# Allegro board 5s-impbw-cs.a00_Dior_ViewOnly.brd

Outline 190 x 92 mm; copper layers: TOP, GND1, IN1, IN2, VCC, IN3, GND2, BOTTOM. Coordinates in mm from the lower left corner of the outline.
Outline path: 0,92 190,92 190,13 188,13 arc(187.29,12.71) 187,12 187,4 180,4 180,8 arc(176,12) 172,8 172,0 119,0 arc(118.71,0.71) 118,1 96,1 arc(95.29,0.71) 95,0 42,0 42,8 arc(38,12) 34,8 34,4 28,4 arc(27.29,3.71) 27,3 27,0 2,0 2,8 arc(1.71,8.71) 1,9 0,9 0,49.7 1.5,49.7 arc(2.21,49.99) 2.5,50.7 2.5,70.5 arc(2.21,71.21) 1.5,71.5 0,71.5 0,92

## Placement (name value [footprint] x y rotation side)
AC1  -  [MX_C0402]  52.53 68.01 90 bottom
AC2  -  [MX_C0402]  50.38 58 0 top
AC3  -  [MX_C0402]  50.24 55.82 0 top
AC4  -  [MX_C0402]  49.1 64.79 270 bottom
AR1  -  [MX_R0402]  50.78 67.28 0 bottom
AR2  -  [MX_R0402]  48.13 57.8 0 top
AR3  -  [MX_R0402]  48.08 56.51 0 top
AR4  -  [MX_R0402]  50.15 64.82 270 bottom
AT2  -  [MX_TPC26B_S4_68]  48.01 63.24 0 top
AT3  -  [MX_TPC26B_S4_68]  50.42 62.63 0 top
AT4  -  [MX_TPC26B_S4_68]  46.2 63.29 0 top
AT6  -  [MX_TPC26B_S4_68]  36.58 63.29 180 bottom
AT9  -  [MX_TPC26B_S4_68]  30.2 61.16 180 bottom
C1  -  [MX_C0402_SMALL]  86.01 22.37 270 top
C2  -  [MX_C0603_SMALL]  87.83 68.99 0 top
C3  -  [MX_C0603_SMALL]  87.83 67.74 0 top
C4  -  [MX_C0603_SMALL]  87.38 38.12 90 top
C5  -  [MX_C0603_SMALL]  89.45 62.27 0 top
C6  -  [MX_C0603_SMALL]  86.76 25.52 0 top
C7  -  [MX_C0603_SMALL]  86.76 24.32 0 top
C8  -  [MX_C0603_SMALL]  69.88 79.95 270 top
C9  -  [MX_C0603_SMALL]  69.88 82.22 90 top
C10  -  [MX_C0402]  69.93 72.81 90 top
C11  -  [MX_C0402]  69.47 64.84 180 top
C12  -  [MX_C0402]  89.25 64.47 0 top
C13  -  [MX_C0402]  69.77 41.38 270 top
C14  -  [MX_C0402]  69.47 62.76 180 top
C15  -  [MX_C0402]  69.34 59 0 top
C16  -  [MX_C0402]  68.94 20.87 270 top
C17  -  [MX_C0402]  86.51 19.47 0 top
C18  -  [MX_C0402]  86.7 26.66 0 top
C19  -  [MX_C0402]  68.35 32.53 270 top
C20  -  [MX_C0402]  69.01 70.02 180 top
C21  -  [MX_C0402]  89.25 63.43 0 top
C22  -  [MX_C0402]  86.67 40.85 270 top
C23  -  [MX_C0402]  59.96 82.05 90 top
C24  -  [MX_C0402]  89.33 40.86 270 top
C25  -  [MX_C0402]  86.79 54.14 90 top
C26  -  [MX_C0402]  91.23 52.95 90 top
C27  -  [MX_C0402]  90.17 52.93 90 top
C28  -  [MX_C0402]  70.87 47.11 270 top
C29  -  [MX_C0402]  87.87 54.13 90 top
C30  -  [MX_C0402]  67.59 61.71 180 top
C31  -  [MX_C0402]  69.37 48.81 0 top
C32  -  [MX_C0402]  87.28 60.14 270 top
C33  -  [MX_C0402]  69.93 34.38 90 top
C34  -  [MX_C0402]  69.93 31.11 270 top
C35  -  [MX_C0402]  69.93 28.06 270 top
C36  -  [MX_C0402]  69.79 23.98 270 top
C37  -  [MX_C0402]  68.86 72.81 90 top
C38  -  [MX_C0402]  86.7 27.7 0 top
C39  -  [MX_C0402]  68.99 66.79 270 top
C40  -  [MX_C0402]  89.23 65.5 0 top
C41  -  [MX_C0402]  69.47 63.8 180 top
C42  -  [MX_C0402]  74.63 17.28 270 top
C43  -  [MX_C0402]  50.14 19.8 180 top
C45  -  [MX_C0402]  54.47 15.33 90 top
C46  -  [MX_C0402]  53.33 20.25 270 top
C48  -  [MX_C0402_SMALL]  165.25 80.03 270 bottom
C49  -  [MX_C0402]  46.2 72.37 180 bottom
C50  -  [MX_C0402]  48.08 72.37 0 bottom
C51  -  [MX_C0402_SMALL]  50.24 70.1 270 top
C52  -  [MX_C0402_SMALL]  52.16 67.5 180 top
C53  -  [MX_C0402_SMALL]  138.31 79.7 90 bottom
C54  -  [MX_C0402_SMALL]  164.07 16.94 90 top
C55  -  [MX_C0402_SMALL]  168.54 22.89 180 top
C56  -  [MX_C0402_SMALL]  167.24 27.84 180 top
C57  -  [MX_C0402_SMALL]  156.59 19.37 270 top
C58  -  [MX_C0402_SMALL]  155.73 19.43 270 top
C59  -  [MX_C0402_SMALL]  161.36 29.61 270 top
C60  -  [MX_C0402]  167.29 29.51 90 top
C61  -  [MX_C0402_SMALL]  166.11 29.61 90 top
C62  -  [MX_C0402_SMALL]  165.12 29.61 90 top
C63  -  [MX_C0402_SMALL]  164.13 29.61 90 top
C64  -  [MX_C0402_SMALL]  163.14 29.61 90 top
C65  -  [MX_C0402_SMALL]  169.14 23.73 180 top
C66  -  [MX_C0402_SMALL]  169.14 24.65 180 top
C67  -  [MX_C0402]  168.43 26.77 0 top
C68  -  [MX_C0402_SMALL]  159.55 16.36 90 top
C69  -  [MX_C0402_SMALL]  95.85 85.54 0 bottom
C70  -  [MX_C0402_SMALL]  113.11 78.6 180 top
C71  -  [MX_C0402_SMALL]  99.93 71.76 0 bottom
C72  -  [MX_C0402_SMALL]  117.3 87.13 180 bottom
C73  -  [MX_C0805_SMALL]  117.21 83.15 90 bottom
C74  -  [MX_C0402_SMALL]  117.27 85.02 180 bottom
C75  -  [MX_C0805_SMALL]  120.14 71.01 180 bottom
C76  -  [MX_C0402_SMALL]  106.15 71.01 90 bottom
C77  -  [MX_C0402_SMALL]  96.74 78.76 90 bottom
C78  -  [MX_C0402_SMALL]  96.72 80.38 270 bottom
C79  -  [MX_C0603_SMALL]  96.73 80.66 180 top
C80  -  [MX_C0402]  95.08 72.14 180 bottom
C81  -  [MX_C0402]  96.79 73.81 0 bottom
C82  -  [MX_C0402_SMALL]  115.01 82.64 90 top
C83  -  [MX_C0402_SMALL]  117.3 87.98 180 bottom
C84  -  [MX_C0402_SMALL]  65.51 85.44 90 bottom
C85  -  [MX_C0402_SMALL]  77.16 85.83 0 top
C86  -  [MX_C0402]  77.17 84.5 180 top
C87  -  [MX_C0402_SMALL]  14.56 68.5 180 bottom
C88  -  [MX_C0402_SMALL]  105.34 70.99 90 top
C91  -  [MX_C0603_SMALL]  182.32 65.24 90 top
C92  -  [MX_C0402]  183.47 65.12 90 top
C93  -  [MX_C0402]  182.58 62.96 270 top
C94  -  [MX_C0603_SMALL]  183.39 58.51 90 top
C95  -  [MX_C0402]  183.06 55.59 180 top
C96  -  [MX_C0402]  183.06 56.74 180 top
C97  -  [MX_C0402_SMALL]  184.1 29.76 270 bottom
C98  -  [MX_C0402_SMALL]  186.97 20.48 180 bottom
C99  -  [MX_C0402_SMALL]  184.1 27.86 90 bottom
C100  -  [MX_C0402_SMALL]  145.49 80.16 0 bottom
C101  -  [MX_C0402_SMALL]  145.38 90.38 0 bottom
C102  -  [MX_C0402_SMALL]  148.56 85.97 90 bottom
C103  -  [MX_C0402_SMALL]  148.56 84.38 270 bottom
C111  -  [MX_C0402]  26.63 81.48 180 bottom
C112  -  [MX_C0603_SMALL]  33.84 83.82 0 bottom
C113  -  [MX_C0402]  28.15 82.34 270 bottom
C114  -  [MX_C0402_SMALL]  41.1 90.01 270 bottom
C115  -  [MX_C0603]  16.38 68.39 90 bottom
C116  -  [MX_C0402]  20.5 63.38 90 top
C121  -  [MX_C0402_SMALL]  96.22 22.19 0 top
C122  -  [MX_C0402_SMALL]  96.22 21.27 0 top
C123  -  [MX_C0402_SMALL]  96.19 20.24 0 top
C124  -  [MX_C0402_SMALL]  96.19 19.35 0 top
C125  -  [MX_C0603]  102.24 9.9 180 bottom
C126  -  [MX_C0402_SMALL]  104.19 35.91 270 bottom
C127  -  [MX_C0402_SMALL]  103.33 35.91 90 bottom
C128  -  [MX_C0402]  149.27 12.15 90 top
C129  -  [MX_C0402]  150.36 12.15 90 top
C130  -  [MX_C0402]  154.37 12.68 90 top
C131  -  [MX_C0402]  155.47 12.68 90 top
C132  -  [MX_C0402_SMALL]  163.78 11.9 180 top
C133  -  [MX_C0402_SMALL]  163.78 11.07 180 top
C134  -  [MX_C0402]  167.63 14.05 90 top
C135  -  [MX_C0402_SMALL]  165.38 11.48 0 top
C136  -  [MX_C0402]  166.57 14.05 90 top
C137  -  [MX_C0402_SMALL]  167.03 10.83 180 top
C138  -  [MX_C0603_SMALL]  145.52 12.31 180 top
C139  -  [MX_C0603_SMALL]  145.52 13.61 180 top
C140  -  [MX_C0402]  147.64 13.26 0 top
C141  -  [MX_C0402]  147.64 12.17 0 top
C142  -  [MX_C0402]  147.97 9.37 270 top
C143  -  [MX_C0402]  146.87 9.37 270 top
C144  -  [MX_C0402_SMALL]  169.29 38.18 0 top
C145  -  [MX_C0402_SMALL]  168.69 14.01 270 top
C146  -  [MX_C0402_SMALL]  174.9 35.07 90 top
C147  -  [MX_C0402_SMALL]  175.94 69.64 90 bottom
C148  -  [MX_C0603]  173.92 64.74 90 bottom
C149  -  [MX_C0402_SMALL]  177.12 39.39 180 bottom
C150  -  [MX_C0402_SMALL]  175.08 39.39 180 bottom
C151  -  [MX_C0402_SMALL]  78.18 9.49 270 bottom
C152  -  [MX_C0805_SMALL]  81.61 8.35 180 bottom
C153  -  [MX_C0402]  61.84 6.99 270 bottom
C154  -  [MX_C0402_SMALL]  6.1 52.98 0 top
C155  -  [MX_C0805_SMALL]  7.39 51.12 90 top
C156  -  [MX_C0402]  159.72 36.16 180 top
C157  -  [MX_C0402_SMALL]  136.19 75.23 270 bottom
C158  -  [MX_C0402_SMALL]  135.31 75.23 270 bottom
C159  -  [MX_C0402]  127.34 70.27 180 bottom
C160  -  [MX_C0402]  129.7 70.3 180 bottom
C161  -  [MX_C0402]  124.93 70.27 180 bottom
C162  -  [MX_C0603]  170.41 81.14 0 top
C163  -  [MX_C0402_SMALL]  168.56 80.97 90 top
C164  -  [MX_C0603]  160.2 86.44 180 top
C165  -  [MX_C0402_SMALL]  163.02 86.2 270 top
C171  -  [MX_C0402_SMALL]  154.92 58.23 270 top
C172  -  [MX_C0603]  157.04 58.47 0 top
C173  -  [MX_C0402_SMALL]  157.94 53.2 180 top
C176  -  [MX_C0402_SMALL]  7.7 76.17 0 top
C177  -  [MX_C0402_SMALL]  9.93 88.18 270 bottom
C178  -  [MX_C0402_SMALL]  179.66 78.33 0 top
C179  -  [MX_C0402_SMALL]  179.86 75.58 90 bottom
C180  -  [MX_C0402_SMALL]  173.56 85.06 0 bottom
C181  -  [MX_C0402_SMALL]  173.56 86.33 0 bottom
C182  -  [MX_C0402_SMALL]  171.35 85.01 0 top
C183  -  [MX_C0402_SMALL]  179.05 80.15 90 bottom
C184  -  [MX_C0402_SMALL]  179.91 80.15 90 bottom
C185  -  [MX_C0402_SMALL]  173.56 84.17 0 bottom
C186  -  [MX_C0402]  179.27 82.82 0 bottom
C187  -  [MX_C0402]  177.37 82.82 180 bottom
C190  -  [MX_C0402_SMALL]  158.8 78.91 270 bottom
C191  -  [MX_C0402_SMALL]  163.02 68.85 90 bottom
C192  -  [MX_C0402_SMALL]  151.39 68.67 0 bottom
C193  -  [MX_C0402_SMALL]  150.99 69.98 90 bottom
C194  -  [MX_C0402_SMALL]  155.93 76.74 270 top
C195  -  [MX_C0402]  150.2 76.27 180 bottom
C196  -  [MX_C0402]  173.47 47.46 0 top
C197  -  [MX_C0402]  173.47 48.51 0 top
C198  -  [MX_C0402]  173.05 53.97 180 top
C199  -  [MX_C0402_SMALL]  180.71 49.24 180 top
C200  -  [MX_C0402_SMALL]  180.71 50.13 180 top
C201  -  [MX_C0402]  29.29 21.43 270 top
C400  -  [MX_C0402_SMALL]  165.68 65.83 180 top
C420  -  [MX_C0402]  183.01 42.06 0 top
C430  -  [MX_C0603]  120.22 3.65 180 bottom
C431  -  [MX_C0402_SMALL]  8.21 77.82 0 top
C432  -  [MX_C0402_SMALL]  10.24 81.25 180 top
C433  -  [MX_C0402_SMALL]  42.01 90.01 270 bottom
C1174  -  [MX_C0603]  57.35 56.74 180 top
C1175  -  [MX_C0603]  54.48 56.68 0 top
C1176  -  [MX_C0603]  59.56 57.11 90 top
C1177  -  [MX_C0603]  54.88 51.97 90 bottom
C1178  -  [MX_C0603]  47.22 34.2 270 bottom
C1179  -  [MX_C0603]  47.06 40.92 90 bottom
C1180  -  [MX_C0402]  46.95 43.36 270 bottom
C1181  -  [MX_C0402]  46.94 38.5 270 bottom
C1182  -  [MX_C0402]  46.94 36.57 90 bottom
C1183  -  [MX_C0402]  87.83 66.59 0 top
C1184  -  [MX_C0402]  76.15 18.88 180 top
C1185  -  [MX_C0402]  80.7 18.86 180 top
C1186  -  [MX_C0402]  69.93 37.89 270 top
C1187  -  [MX_C0402]  74.47 50.23 180 top
C1188  -  [MX_C0402]  73 18.86 180 top
C1189  -  [MX_C0402]  47.54 17.15 270 top
C1190  -  [MX_C0402]  47.88 20.44 0 top
C1191  -  [MX_C0402]  46.48 17.15 270 top
C1192  -  [MX_C0603]  58.18 19.21 90 top
C1193  -  [MX_C0402]  56.84 19.02 90 top
C1194  -  [MX_C0402]  57.99 16.47 270 top
C1195  -  [MX_C0603]  59.32 16.25 270 top
C9200  -  [MX_C0603_SMALL]  154.31 65.33 90 top
C9206  -  [MX_C0402]  155.38 17.66 270 top
C9207  -  [MX_C0402_SMALL]  157.37 17.73 90 top
C9209  -  [MX_C0402_SMALL]  156.41 22.65 0 top
C9210  -  [MX_C0402_SMALL]  168.27 25.66 180 top
C9211  -  [MX_C0402_SMALL]  159.44 29.58 270 top
C9212  -  [MX_C0402_SMALL]  168.53 21.85 180 top
C9213  -  [MX_C0402_SMALL]  162.2 29.61 270 top
C9214  -  [MX_C0402_SMALL]  161.22 16.42 90 top
C9215  -  [MX_C0402_SMALL]  158.66 16.36 90 top
C9217  -  [MX_C0402]  183.03 43.15 0 top
C9218  -  [MX_C0402]  183.03 45.72 0 top
C9219  -  [MX_C0402]  183.03 46.81 0 top
C9220  -  [MX_C0402_SMALL]  6.41 81.09 270 top
CA10  -  [MX_C0402_SMALL]  164.98 54.68 90 top
CA11  -  [MX_C0402_SMALL]  161.37 53.35 0 top
CA12  -  [MX_C0603_SMALL]  163.35 53.17 0 top
CA13  -  [MX_C0603_SMALL]  165.08 59.32 90 top
CB1  -  [MX_R0402_SMALL]  124.92 32.29 270 top
CB2  -  [MX_R0402_SMALL]  125.69 43.65 180 top
CB3  -  [MX_C0402_SMALL]  125.78 32.27 90 top
CB4  -  [MX_R0402_SMALL]  129.95 32.3 270 top
CB5  -  [MX_C0402_SMALL]  130.01 43.75 180 top
CB6  -  [MX_R0402_SMALL]  128.46 43.75 180 top
CB7  -  [MX_C0603_SMALL]  96.29 89.74 90 bottom
CE1  -  [MX_C7343D_H75]  96.85 65.49 270 bottom
CKC1  -  [MX_C0402]  15.63 47.99 90 bottom
CKC2  -  [MX_C0402]  15.64 46.09 270 bottom
CKC3  -  [MX_C0402]  35.13 74.44 270 top
CKC4  -  [MX_C0402]  38.36 78.95 90 bottom
CKC5  -  [MX_C0402]  149.3 71.48 270 bottom
CKC6  -  [MX_C0402]  149.29 73.53 90 bottom
CKC7  -  [MX_C0402]  36.3 74.41 90 top
CKR1  -  [MX_R0402]  16.72 46.95 90 bottom
CKR2  -  [MX_R0402]  12.83 39.86 270 bottom
CKR3  -  [MX_R0402]  35.25 72.14 90 top
CKR4  -  [MX_R0402]  38.58 75.23 90 bottom
CKR5  -  [MX_R0402]  36.28 72.14 90 top
CKRN1  -  [MX_2R4P0402_H18]  16 42.87 270 bottom
CKRN2  -  [MX_2R4P0402_H18]  39.83 71.25 0 top
CKX1  -  [MX_XTAL_4P_126X98_HELE]  13.3 46.78 90 bottom
CN1  -  [MX_FPC_CON_5P_39_2HOLD_RA]  25 85 0 bottom
CON1  -  [MX_WTOB_2P_49_2H_ACES]  167.38 84.9 180 bottom
CON2  -  [MX_FPC_26P_20_4HD_RA_PANASO]  103.08 85.62 180 top
CON3  -  [MX_SATA_CON_22P_50_4H_RA_P2]  188.32 56.53 270 bottom
CON4  -  [MX_WTOB_4P_31_2H_RA]  186.11 17.2 180 bottom
CON5  -  [MX_FPC_1X12P_20_2H]  86.71 78.56 180 top
CON6  -  [MX_WTOB_11P_31_2HOLD_ACES]  156 85.99 90 bottom
CON7  -  [MX_WTOB_4P_49_RA]  13 65.5 90 bottom
CON8  -  [MX_WTOB_9P_59_2HD_RA_ACES]  127.01 79.4 0 bottom
CON9  -  [MX_FPC_7P_20_2HOLD_RA_ENT_T]  134 7.8 180 bottom
CON10  -  [MX_BTOB_60P_20_F_PANA]  6 81.99 270 bottom
CON11  -  [MX_FPC_18P_20_2HD_RA_ACE_B]  181 88 0 bottom
CONSATA  -  [MX_MINI_PCI_67P_20_4HD_FOXN]  101.38 23.08 270 bottom
CONWIFI  -  [MX_MINI_PCI_67P_20_4H_FXN]  175.43 51.1 90 bottom
CR1  -  [MX_LED_2P_63X31_H16]  127.52 85.75 0 top
CR2  -  [MX_LED_2P_63X31_H16]  112.96 85.74 0 top
CR3  -  [MX_LED_2P_63X31_H16]  113.75 77.12 0 top
CR4  -  [MX_LED_2P_63X31_H16]  120.91 85.74 0 top
CR5  -  [MX_LED_2P_63X31_H16]  117.43 77.17 0 top
CR6  -  [MX_LED_2P_63X31_H16]  120.99 77.19 0 top
CR7  -  [MX_LED_2P_63X31_H16]  117.61 85.74 0 top
CR8  -  [MX_LED_2P_63X31_H16]  110.39 77.02 0 top
CR9  -  [MX_LED_2P_63X31_H16]  124.19 85.75 0 top
CX3  -  [MX_C0402]  177.01 47.37 90 top
CX4  -  [MX_C0402]  178.11 47.37 90 top
D1  -  [MX_SOT323]  167.41 79.55 0 bottom
D2  -  [MX_SOD323_H37]  49.99 80.87 270 top
D3C5  -  [MX_C0402]  58.95 77.98 270 top
D3C7  -  [MX_C0402]  69.79 25.99 90 top
D3C8  -  [MX_C0402]  60 77.96 270 top
D3CE2  -  [MX_C0603_SMALL]  56.21 56.4 90 bottom
D3CE3  -  [MX_C0603_SMALL]  56.23 51.88 90 bottom
D3CE4  -  [MX_C0603_SMALL]  54.84 55.47 270 bottom
D3CE5  -  [MX_C0603_SMALL]  69.09 71.19 180 top
D3CE6  -  [MX_C0603_SMALL]  56.54 49.34 270 bottom
D3CE7  -  [MX_C0603_SMALL]  67.67 57.01 180 top
D3CE8  -  [MX_C0603_SMALL]  69.57 50.49 270 top
D3CE9  -  [MX_C0603_SMALL]  56.21 54.08 270 bottom
D3CE20  -  [MX_C0402]  86.51 20.54 0 top
D3CE21  -  [MX_C0402]  68.73 23.99 270 top
D3CE22  -  [MX_C0402]  56.64 41.54 270 bottom
D3CE23  -  [MX_C0402]  88.27 31.72 90 top
D3CE24  -  [MX_C0402]  88.34 60.14 270 top
D3CE25  -  [MX_C0402]  68.86 28.06 270 top
D3CE26  -  [MX_C0402]  69.19 52.72 0 top
D3CE27  -  [MX_C0402]  56.65 46.12 90 bottom
D3CE28  -  [MX_C7343D_H79]  101.8 65.48 270 bottom
D3CE36  -  [MX_C0402]  88.94 54.13 90 top
D3CE37  -  [MX_C0402]  87.71 40.85 270 top
D3CE38  -  [MX_C0402]  68.68 81.22 90 top
D3CE39  -  [MX_C0402]  59.97 80.15 270 top
D3CE40  -  [MX_C0603_SMALL]  61.21 82.14 90 top
D3CE41  -  [MX_C0603_SMALL]  61.2 79.94 270 top
D4  -  [MX_SOD323_H37]  9.98 82.77 180 top
D5  -  [MX_S0402_AMAZ]  117.9 71 270 bottom
D6  -  [MX_SOD323_H37]  102.31 79.09 0 top
D7  -  [MX_SOD323_H37]  94.09 86.27 90 bottom
D8  -  [MX_SOT323]  107.51 71.82 0 top
D9  -  [MX_SOD323_H35]  187.05 23.3 90 bottom
D10  -  [MX_S0402_AMAZ]  21.45 82.52 180 bottom
D11  -  [MX_S0402_AMAZ]  31.57 89.88 90 bottom
D12  -  [MX_S0402_AMAZ]  31.57 88.1 270 bottom
D13  -  [MX_SOD323_H37]  14.91 60.39 270 bottom
D14  -  [MX_SOD323_H37]  177.5 63.09 270 top
D15  -  [MX_SOT323]  57.39 10.07 0 bottom
D16  -  [MX_S0402_AMAZ]  64.41 7.21 90 bottom
D17  -  [MX_ESD_2P_33_39X24_AMA]  79.45 9.49 90 bottom
D18  -  [MX_SOT323]  157.43 38.41 90 top
D19  -  [MX_ESD_2P_33_39X24_AMA]  5.92 50.87 270 top
D20  -  [MX_S0402_AMAZ]  125.52 71.47 180 bottom
D21  -  [MX_S0402_AMAZ]  127.55 71.46 180 bottom
D22  -  [MX_S0402_AMAZ]  129.58 71.44 180 bottom
D24  -  [MX_SOD323_H37]  151.52 78.98 180 bottom
D9200  -  [MX_SOD323_H37]  153.96 62.07 90 top
D9201  -  [MX_SOT323]  81.16 89.57 180 bottom
DIMM1  -  [MX_DDR3_DIMM_204P_24_4HL_DA]  63.6 48.5 90 bottom
E2  -  [MX_HD_2X5P_50_K1K3K5K6K79_J]  89.61 85.5 0 bottom
F1  -  [MX_POLYSWITCH_2P_1206]  33.81 85.87 180 bottom
F3CB4  -  [MX_C0603]  134.82 81.75 180 top
F3J1  -  [MX_FPC_10P_20_2H_RA_AC_H79]  135.79 85.28 180 top
F3R2  -  [MX_R0402]  137.57 82.52 90 bottom
F3R3  -  [MX_R0402]  140.05 80.15 0 bottom
F3R7  -  [MX_R0402]  137.56 89.62 90 bottom
F3R8  -  [MX_R0402]  140.01 79.04 0 bottom
F3R9  -  [MX_R0402]  137.56 84.85 270 bottom
F3R10  -  [MX_R0402]  142.71 79.47 270 bottom
F3R11  -  [MX_R0402]  143.84 79.5 270 bottom
F3R13  -  [MX_R0402]  139.82 82.94 180 top
F3R14  -  [MX_R0402]  136.86 80.99 90 top
F3U1  -  [MX_SOIC_8P_50_213X311]  141.12 85.66 0 bottom
GC1  -  [MX_C0402]  78.44 13.05 90 top
GC2  -  [MX_C0402]  81.2 13.05 90 top
GC3  -  [MX_C0402]  93.51 5.4 90 bottom
GC4  -  [MX_C0402]  97.13 7.75 180 bottom
GR1  -  [MX_R0402]  26.24 23.46 90 bottom
GR2  -  [MX_R0402]  23.06 25.11 270 top
GR3  -  [MX_R0402]  43.21 23.94 270 top
GR4  -  [MX_R0402]  59.13 4.92 0 top
GR5  -  [MX_R0402]  82.7 13.05 270 top
GR6  -  [MX_R0402]  80.6 16.02 270 top
GR7  -  [MX_R0402]  62.05 4.92 180 top
GR8  -  [MX_R0402]  70.1 15.1 0 top
GR10  -  [MX_R0402]  58.6 6.06 0 top
GR11  -  [MX_R0402]  70.1 16.22 0 top
GR12  -  [MX_R0402]  62.05 5.96 0 top
GR13  -  [MX_R0402]  58.52 7.15 180 top
GR14  -  [MX_R0402]  121.62 27.04 270 top
GR15  -  [MX_R0402]  81.75 15.99 270 top
GR16  -  [MX_R0402]  83.81 15.98 270 top
GR17  -  [MX_R0402]  62.05 8.18 180 top
GR18  -  [MX_R0402]  62.05 7.15 180 top
GR19  -  [MX_R0402]  58.88 8.35 180 top
GR20  -  [MX_R0402]  83.92 13.05 270 top
GR21  -  [MX_R0402]  84.84 15.99 270 top
GR22  -  [MX_R0402]  85.1 12.99 90 top
GR23  -  [MX_R0402]  82.78 15.99 90 top
GR24  -  [MX_R0402]  99.56 8.13 0 bottom
GR25  -  [MX_R0402]  98.94 9.93 90 bottom
GR26  -  [MX_R0402]  93.69 9.78 90 bottom
GR27  -  [MX_R0402]  100.11 9.94 270 bottom
GR28  -  [MX_R0402]  32.67 18.85 90 bottom
GR29  -  [MX_R0402]  33.73 18.85 90 bottom
GR30  -  [MX_R0402]  31.35 18.85 90 bottom
GR31  -  [MX_R0402]  34.88 24.1 90 bottom
GR32  -  [MX_R0402]  32.46 24.1 90 bottom
GR33  -  [MX_R0402]  33.73 24.1 90 bottom
GR34  -  [MX_R0402]  31.19 24.1 90 bottom
GR35  -  [MX_R0402]  33.73 21.18 90 bottom
GR36  -  [MX_R0402]  31.35 21.18 90 bottom
GR37  -  [MX_R0402]  36.02 24.1 270 bottom
GR38  -  [MX_R0402]  32.46 21.18 90 bottom
GR39  -  [MX_R0402]  165.93 16.18 90 top
GU1  -  [MX_SOIC_14P_26_201X252]  88.82 5.88 90 bottom
GU2  -  [MX_SC70_C5]  96.41 9.64 180 bottom
H1  -  [MX_SMT_NUT_CT197B63D47_H102]  41.83 22.38 180 bottom
H2  -  [MX_SMT_NUT_CT197B63D47_H102]  21.83 22.38 180 bottom
H3  -  [MX_SMT_NUT_CT197B63D47_H102]  21.83 78.78 180 bottom
H4  -  [MX_SMT_NUT_CT197B63D47_H102]  41.83 78.78 180 bottom
H9  -  [MX_SMT_NUT_CT217B160D130]  147.18 51.1 180 bottom
H11  -  [MX_SMT_NUT_CT217B160D130]  179.63 23.07 180 bottom
H19  -  [MX_TPC26B_S4_68]  35.05 68.03 180 bottom
H6505  -  [NB_H_2D_D87N_DO83X102_P2_V4]  187 80.5 0 top
H6506  -  [NB_H_2D_D87N_D83_M2_P2_V4]  183.5 10.5 0 top
H6507  -  [NB_H_S276D87N_M2_P2_V4#2]  98 47.49 0 top
H6508  -  [NB_H_S276D87N_M2_P2_V4]  15 88.5 0 top
H6509  -  [NB_H_2D_DO102X83_D87N_P2_V4]  5.5 3 0 top
H6510  -  [MX_NUT_CT217B118D47_H165]  13 79 180 bottom
H6511  -  [MX_HOLE_C118D118N]  141.63 23.08 0 top
H6512  -  [MX_HOLE_C59D59N]  146.03 23.08 0 top
HC1  -  [MX_C0402]  67.42 68.09 90 top
HC3  -  [MX_C0402]  15.9 31.03 180 bottom
HC5  -  [MX_C0805]  50.32 59.04 270 bottom
HC6  -  [MX_C0402]  34.11 54.78 0 top
HC7  -  [MX_C0402]  99 4.18 270 bottom
HC8  -  [MX_C0402_SMALL]  16.03 27.83 180 bottom
HQ1  -  [MX_SOT23_H43]  39.12 17.9 0 bottom
HQ2  -  [MX_SOT23_H43]  66.3 65.46 180 top
HQ3  -  [MX_SOT23_H43]  77.36 89.19 180 bottom
HR2  -  [MX_R0402]  27.56 21.05 90 bottom
HR3  -  [MX_R0402]  26.52 21.05 90 bottom
HR4  -  [MX_R0402]  27.48 23.46 90 bottom
HR5  -  [MX_R0402]  19.58 26.05 0 top
HR6  -  [MX_R0402]  41.85 18.06 90 bottom
HR7  -  [MX_R0402]  45.59 23.94 270 top
HR8  -  [MX_R0402]  46.75 23.94 270 top
HR9  -  [MX_R0402]  44.35 23.94 270 top
HR10  -  [MX_R0402]  63.55 70.2 270 top
HR11  -  [MX_R0402]  62.03 68.9 180 top
HR12  -  [MX_R0402]  67.26 71.29 270 top
HR13  -  [MX_R0402]  62.8 66.72 180 top
HR14  -  [MX_R0402]  62.56 64.09 270 top
HR15  -  [MX_R0402]  63.6 64.09 270 top
HR16  -  [MX_R0402]  21.75 55.14 90 top
HR21  -  [MX_R0402_SHORT]  15.86 32.16 0 bottom
HR22  -  [MX_R0402]  28.91 21.2 90 bottom
HR23  -  [MX_R0402]  28.91 18.05 270 bottom
HR24  -  [MX_R0402]  28.65 23.46 90 bottom
HR27  -  [MX_R0402_SHORT]  15.76 29.9 0 bottom
HR28  -  [MX_R0402_SHORT]  26.48 24.15 90 top
HR29  -  [MX_R0402_SHORT]  15.86 28.83 0 bottom
HR31  -  [MX_R0402]  26.48 21.46 270 top
HR32  -  [MX_R0805]  52.37 58.81 270 bottom
HR33  -  [MX_R0805]  12.37 30.86 0 bottom
HR34  -  [MX_R0805]  66.93 17.9 0 top
HR37  -  [MX_R0402]  37.67 24.1 90 top
HR38  -  [MX_R0402]  36.53 24.1 90 top
HR39  -  [MX_R0402]  31.95 24.1 90 top
HR40  -  [MX_R0402]  33.1 24.1 90 top
HR41  -  [MX_R0402]  34.24 24.1 90 top
HR42  -  [MX_R0402]  35.38 24.1 90 top
HR43  -  [MX_R0402]  50.45 55.35 0 bottom
HR44  -  [MX_R0402]  30.81 24.1 270 top
HR45  -  [MX_R0402]  16.51 58.87 90 bottom
HR46  -  [MX_R0402]  100.19 4.25 270 bottom
HR47  -  [MX_R0402]  98.98 6.41 270 bottom
HR48  -  [MX_R0402_SMALL]  183.21 29.76 270 bottom
HT1  -  [MX_TPC26B_S4_68]  21.64 26.61 180 bottom
HT2  -  [MX_TPC26B_S4_68]  18.98 27.68 180 bottom
HT3  -  [MX_TPC26B_S4_68]  23.32 28.72 180 bottom
HT4  -  [MX_TPC26B_S4_68]  26.06 28.82 180 bottom
HT5  -  [MX_TPC26B_S4_68]  25.12 32.17 180 bottom
HT6  -  [MX_TPC26B_S4_68]  27.69 21.81 180 bottom
HT7  -  [MX_TPC26B_S4_68]  27.28 30.78 180 bottom
HT8  -  [MX_TPC26B_S4_68]  25.2 25.9 0 top
HT9  -  [MX_TPC26B_S4_68]  27.89 25.04 180 bottom
HT10  -  [MX_TPC26B_S4_68]  27.71 28.26 180 bottom
HT11  -  [MX_TPC26B_S4_68]  28.65 31.84 180 bottom
HT12  -  [MX_TPC26B_S4_68]  28.78 29.68 180 bottom
HT13  -  [MX_TPC26B_S4_68]  49.38 21.86 0 top
HT14  -  [MX_TPC26B_S4_68]  52.86 3.12 180 bottom
HT15  -  [MX_TPC26B_S4_68]  86.18 13.86 180 bottom
HT16  -  [MX_TPC26B_S4_68]  54.64 3.17 180 bottom
HT17  -  [MX_TPC26B_S4_68]  47.14 21.51 0 top
HT18  -  [MX_TPC26B_S4_68]  22.96 26.08 0 top
HT19  -  [MX_TPC26B_S4_68]  22.71 17.9 0 top
HT20  -  [MX_TPC26B_S4_68]  56.41 3.17 180 bottom
HT21  -  [MX_TPC26B_S4_68]  17.78 41.47 0 top
HT22  -  [MX_TPC26B_S4_68]  58.19 3.14 180 bottom
HT23  -  [MX_TPC26B_S4_68]  17.63 36.26 0 top
HT24  -  [MX_TPC26B_S4_68]  17.93 36.59 180 bottom
HT25  -  [MX_TPC26B_S4_68]  54.59 7.89 0 top
HT26  -  [MX_TPC26B_S4_68]  29.8 18.13 180 bottom
HT27  -  [MX_TPC26B_S4_68]  54.41 11.35 180 bottom
HT28  -  [MX_TPC26B_S4_68]  30.61 26.26 180 bottom
HT29  -  [MX_TPC26B_S4_68]  28.65 23.41 180 bottom
HT30  -  [MX_TPC26B_S4_68]  30.56 29.2 180 bottom
HT31  -  [MX_TPC26B_S4_68]  30.3 31.18 180 bottom
HT32  -  [MX_TPC26B_S4_68]  32.11 52.98 180 bottom
HT33  -  [MX_TPC26B_S4_68]  31.12 51.38 180 bottom
HT34  -  [MX_TPC26B_S4_68]  29.92 23.28 0 top
HT35  -  [MX_TPC26B_S4_68]  58.73 11.8 180 bottom
HT36  -  [MX_TPC26B_S4_68]  67.03 10.63 0 top
HT37  -  [MX_TPC26B_S4_68]  41.94 29 180 bottom
HT38  -  [MX_TPC26B_S4_68]  54.5 11.56 0 top
HT39  -  [MX_TPC26B_S4_68]  17.45 31.08 0 top
HT40  -  [MX_TPC26B_S4_68]  20.91 66.08 180 bottom
HT41  -  [MX_TPC26B_S4_68]  28.78 54.96 180 bottom
HT42  -  [MX_TPC26B_S4_68]  20.47 68.19 180 bottom
HT43  -  [MX_TPC26B_S4_68]  29.57 50.51 180 bottom
HT44  -  [MX_TPC26B_S4_68]  22.12 67.38 180 bottom
HT45  -  [MX_TPC26B_S4_68]  23.73 54.45 180 bottom
HT46  -  [MX_TPC26B_S4_68]  23.83 57.95 180 bottom
HT47  -  [MX_TPC26B_S4_68]  19.33 66.86 180 bottom
HT48  -  [MX_TPC26B_S4_68]  46.56 32.17 0 top
HT49  -  [MX_TPC26B_S4_68]  18.26 21.96 0 top
HT50  -  [MX_TPC26B_S4_68]  18.72 68.95 180 bottom
HT51  -  [MX_TPC26B_S4_68]  19.08 20.01 0 top
HT52  -  [MX_TPC26B_S4_68]  41.99 70.22 180 bottom
HT53  -  [MX_TPC26B_S4_68]  44.71 68.42 180 bottom
HT54  -  [MX_TPC26B_S4_68]  43.89 26.1 0 top
HT55  -  [MX_TPC26B_S4_68]  27.43 52.37 180 bottom
HT56  -  [MX_TPC26B_S4_68]  27.76 50.61 180 bottom
HT57  -  [MX_TPC26B_S4_68]  40.44 67.17 180 bottom
HT58  -  [MX_TPC26B_S4_68]  29.24 52.52 180 bottom
HT60  -  [MX_TPC26B_S4_68]  30.66 62.96 180 bottom
HT61  -  [MX_TPC26B_S4_68]  45.35 40.95 0 top
HT62  -  [MX_TPC26B_S4_68]  21.62 58.67 180 bottom
HT63  -  [MX_TPC26B_S4_68]  40.54 71.44 0 top
HT65  -  [MX_TPC26B_S4_68]  23.52 52.67 180 bottom
HT66  -  [MX_TPC26B_S4_68]  41.89 66.13 180 bottom
HT67  -  [MX_TPC26B_S4_68]  26.01 53.46 180 bottom
HT68  -  [MX_TPC26B_S4_68]  52.15 62.48 0 top
HT70  -  [MX_TPC26B_S4_68]  41.23 58.72 180 bottom
HT71  -  [MX_TPC26B_S4_68]  46.76 60.29 0 top
HT72  -  [MX_TPC26B_S4_68]  48.52 60.19 0 top
HT81  -  [MX_TPC26B_S4_68]  12.97 34.23 0 top
HT82  -  [MX_TPC26B_S4_68]  14.61 34.87 0 top
HT83  -  [MX_TPC26B_S4_68]  15.8 33.53 0 top
HT84  -  [MX_TPC26B_S4_68]  17.45 32.88 0 top
HT85  -  [MX_TPC26B_S4_68]  17.65 38.04 0 top
HT86  -  [MX_TPC26B_S4_68]  19.74 37.1 180 bottom
HT87  -  [MX_TPC26B_S4_68]  12.35 32.5 0 top
HT89  -  [MX_TPC26B_S4_68]  17.86 38.96 180 bottom
HT90  -  [MX_TPC26B_S4_68]  18.09 39.74 0 top
HT91  -  [MX_TPC26B_S4_68]  21.36 37.74 180 bottom
HT92  -  [MX_TPC26B_S4_68]  20.09 39.21 180 bottom
HT93  -  [MX_TPC26B_S4_68]  175.52 20.92 180 bottom
HT94  -  [MX_TPC26B_S4_68]  174.14 22.22 180 bottom
HT95  -  [MX_TPC26B_S4_68]  14.26 44 0 top
HT96  -  [MX_TPC26B_S4_68]  155.35 70.3 180 bottom
HT97  -  [MX_TPC26B_S4_68]  153.9 73.58 180 bottom
HT98  -  [MX_TPC26B_S4_68]  113.06 69.03 180 bottom
HT99  -  [MX_TPC26B_S4_68]  123.22 71.32 180 bottom
HU1  -  [MX_SC70_C5]  65.39 69.32 90 top
HU4  -  [MX_SC70_C5]  96.41 5.38 180 bottom
J1  -  [MX_WTOB_5P_49_2H_RA_ENTER]  71.5 4.9 180 bottom
L2  -  [MX_L0603]  147.11 16.31 0 top
L3  -  [MX_L0603]  170.27 29.1 180 top
L4  -  [MX_L0402_SMALL]  160.25 87.98 180 bottom
L5  -  [MX_CHOKE_4P_79X47_FUKUI]  161.68 85.34 270 bottom
L6  -  [MX_CHOKE_4P_79X47_FUKUI]  33.95 89.04 0 bottom
L7  -  [MX_L0603_SMALL]  63.07 6.84 90 bottom
L8  -  [MX_L0603_SMALL]  16.17 49.54 0 bottom
L9  -  [MX_L0603_SMALL]  129.51 69.17 180 bottom
L10  -  [MX_L0603_SMALL]  127.23 69.14 180 bottom
L11  -  [MX_L0603_SMALL]  124.94 69.13 180 bottom
MC1  -  [MX_C0402_SMALL]  39.02 81.68 0 top
MC2  -  [MX_C0402_SMALL]  39.02 80.86 0 top
MC3  -  [MX_C0402_SMALL]  31.05 84.07 180 top
MC4  -  [MX_C0402_SMALL]  31.1 84.89 180 top
NOREF  -  [unnamed]  199.42 180.92 0 top
NOREF#2  -  [#2]  109.7 24.55 0 top
NOREF#3  -  [unnamed#3]  18.34 8.48 0 top
NOREF#4  -  [unnamed]  199.42 5.08 180 top
NOREF#5  -  [unnamed#3]  -9.42 172.03 0 top
NOREF#6  -  [unnamed#3]  199.42 161.87 0 top
NOREF#7  -  [#2]  4.98 37.96 90 top
NOREF#8  -  [#2]  4.6 35.17 90 top
NOREF#9  -  [#2]  92.69 14.88 0 top
NOREF#10  -  [unnamed#3]  177.4 85.54 0 top
NOREF#11  -  [unnamed]  -9.42 5.08 180 top
NOREF#12  -  [#2]  4.9 34.81 90 top
NOREF#13  -  [unnamed]  182.32 74.9 0 top
NOREF#14  -  [unnamed]  14.05 7.46 0 top
NOREF#15  -  [#2]  4.98 43.22 90 top
NOREF#16  -  [#2]  146.31 32.99 0 top
NOREF#17  -  [#2]  4.98 13.53 90 top
NOREF#18  -  [#2]  4.98 25.57 90 top
NOREF#19  -  [unnamed#3]  176.84 16.32 0 top
NOREF#20  -  [unnamed#3]  199.42 24.13 180 top
NOREF#21  -  [#2]  5.01 15.56 90 top
NOREF#22  -  [#2]  34 -31.08 0 top
NOREF#23  -  [#2]  90.91 1.69 0 top
NOREF#24  -  [#2]  197.82 89.76 90 top
NOREF#25  -  [unnamed]  -9.42 180.92 0 top
NOREF#26  -  [#2]  116.21 50.79 0 top
NOREF#27  -  [#2]  108.66 38.32 0 top
NOREF#28  -  [unnamed#3]  -9.42 13.97 180 top
NOREF#29  -  [#2]  5.01 20.54 90 top
NOREF#30  -  [#2]  105.56 29.33 0 top
NOREF#31  -  [unnamed#3]  167.34 65.42 180 bottom
NOREF#32  -  [#2]  197.82 89.76 270 bottom
NOREF#33  -  [unnamed#3]  -9.42 166.95 180 bottom
NOREF#34  -  [#2]  138.46 84.24 180 bottom
NOREF#35  -  [unnamed#3]  -9.42 19.05 0 bottom
NOREF#36  -  [unnamed#3]  199.42 156.79 180 bottom
NOREF#37  -  [unnamed#3]  199.42 29.21 0 bottom
NOREF#38  -  [unnamed#3]  16.38 5.4 180 bottom
NOREF#39  -  [unnamed#3]  180.54 15.84 180 bottom
P2  -  [MX_WTOB_CON_40P_20_4H_SC]  157.5 6.5 180 bottom
PC3  -  [MX_C0402]  28.63 60.63 0 top
PC4  -  [MX_C0402]  26.54 61.5 270 top
PC6  -  [MX_C0402]  46.01 75.72 90 top
PC7  -  [MX_C0805]  13.76 73.37 270 bottom
PC8  -  [MX_C0402]  56.95 77.03 180 top
PC9  -  [MX_C0402]  56.95 78.07 180 top
PC10  -  [MX_C0402]  56.96 76 180 top
PC11  -  [MX_C0805]  11.86 83.3 0 bottom
PC12  -  [MX_C0402]  18.49 57.12 270 top
PC13  -  [MX_C0805]  17.6 76.8 90 bottom
PC14  -  [MX_C0805]  17.93 80.99 270 bottom
PC15  -  [MX_C0402]  16.71 61.16 90 bottom
PC16  -  [MX_C0402]  30.86 56.33 180 top
PC17  -  [MX_C0402]  33.83 72 90 top
PC18  -  [MX_C0402]  33.1 67.77 270 top
PC19  -  [MX_C0402]  24.17 59.78 90 top
PC20  -  [MX_C0402]  33.35 58.87 180 top
PC21  -  [MX_C0805]  54.77 76.45 180 bottom
PC23  -  [MX_C0402]  26.22 59.55 270 top
PC24  -  [MX_C0402]  37.5 58.16 0 top
PC25  -  [MX_C0402]  35.36 59.4 0 top
PC26  -  [MX_C0402]  35.99 55.31 270 top
PC27  -  [MX_C0805]  51.71 78.5 180 bottom
PC28  -  [MX_C0402]  47.91 82.29 270 bottom
PC29  -  [MX_C0805]  51.87 82.73 180 bottom
PC30  -  [MX_C0402]  33.95 62.61 0 top
PC31  -  [MX_C0402]  56.02 70.33 270 top
PC32  -  [MX_C0805]  27.83 78.43 180 bottom
PC33  -  [MX_C0402]  28.52 59.56 180 top
PC34  -  [MX_C0402]  26.09 56.33 0 top
PC35  -  [MX_C0402]  20.68 56.87 90 top
PC36  -  [MX_C0402]  28.57 56.45 180 top
PC37  -  [MX_C0402]  24.77 61.7 270 top
PC38  -  [MX_C0402]  32.45 62.25 270 top
PC39  -  [MX_C0402]  29.1 80.15 0 bottom
PC40  -  [MX_C0402]  11.5 38.8 90 bottom
PC42  -  [MX_C0603]  52.53 84.55 180 bottom
PC43  -  [MX_C0402]  179.27 67.4 270 bottom
PC44  -  [MX_C0603_SMALL]  10.29 50.64 270 top
PC45  -  [MX_C0603_SMALL]  9.07 50.64 270 top
PC46  -  [MX_C0402_SMALL]  7.44 59.91 0 top
PC47  -  [MX_C0603_SMALL]  11.51 48.33 270 top
PC48  -  [MX_C0805_SMALL]  13.15 49.79 90 top
PC49  -  [MX_C0805_SMALL]  16.6 49.8 90 top
PC50  -  [MX_C0805_SMALL]  14.87 49.8 270 top
PC51  -  [MX_C0805_SMALL]  18.33 49.81 270 top
PC52  -  [MX_C0603_SMALL]  136.95 40.7 0 top
PC53  -  [MX_C0603_SMALL]  138.05 36.12 180 top
PC54  -  [MX_C0402_SMALL]  139.51 40.49 0 top
PC55  -  [MX_C0402]  6.61 60.85 180 top
PC56  -  [MX_C0402]  6.94 69.64 180 top
PC57  -  [MX_C0402_SMALL]  140.52 46.5 90 bottom
PC58  -  [MX_C0402_SMALL]  136.09 68.75 270 bottom
PC59  -  [MX_C0603_SMALL]  143.56 48.36 0 bottom
PC60  -  [MX_C0402_SMALL]  140.87 47.8 180 bottom
PC61  -  [MX_C0402_SMALL]  141.36 46.5 90 bottom
PC63  -  [MX_C0805_SMALL]  140.12 70.78 270 bottom
PC64  -  [MX_C0603_SMALL]  143.13 53.81 0 bottom
PC65  -  [MX_C0402_SMALL]  136.37 49.08 0 bottom
PC66  -  [MX_C0402_SMALL]  140.79 59.85 0 bottom
PC67  -  [MX_C0805_SMALL]  137.08 71.44 180 bottom
PC68  -  [MX_C0805_SMALL]  137.08 73.32 180 bottom
PC69  -  [MX_C0402]  136.25 50.11 180 bottom
PC70  -  [MX_C0402_SMALL]  139.21 55.39 0 bottom
PC71  -  [MX_C0402_SMALL]  140.79 57.42 270 top
PC72  -  [MX_C0402_SMALL]  139.21 56.21 180 bottom
PC73  -  [MX_C0402_SMALL]  10.92 11.77 90 top
PC74  -  [MX_C0402]  12.55 15.89 180 top
PC75  -  [MX_C0603]  9.59 16.66 180 bottom
PC76  -  [MX_C0603_SMALL]  13.75 13.62 270 top
PC77  -  [MX_C0402]  9.24 18.08 180 bottom
PC78  -  [MX_C0402]  9.74 20.71 180 bottom
PC79  -  [MX_C0402]  18.47 18.85 90 top
PC80  -  [MX_C0402]  19.52 18.85 90 top
PC81  -  [MX_C0402]  17.23 14.48 0 top
PC82  -  [MX_C0402]  16.7 11.59 270 top
PC83  -  [MX_C0603_SMALL]  15.42 13.6 270 top
PC84  -  [MX_C0402]  14.79 23.38 90 bottom
PC85  -  [MX_C0603]  13.05 22.07 180 top
PC87  -  [MX_C0805_SMALL]  7.2 26.79 180 bottom
PC88  -  [MX_C0805_SMALL]  3.15 23.87 0 bottom
PC90  -  [MX_C0402_SMALL]  6.89 28.11 180 bottom
PC91  -  [MX_C0603_SMALL]  2.4 27.08 0 bottom
PC92  -  [MX_C0603]  2.69 34.74 180 bottom
PC94  -  [MX_C0603]  8.33 31.56 270 bottom
PC95  -  [MX_C0603]  15.17 38.11 270 top
PC96  -  [MX_C0603]  11.2 38.11 270 top
PC97  -  [MX_C0805_SMALL]  10.05 40.63 180 bottom
PC98  -  [MX_C0805_SMALL]  10.05 42.35 180 bottom
PC99  -  [MX_C0805_SMALL]  10.06 44.08 180 bottom
PC100  -  [MX_C0805_SMALL]  2.17 46.49 270 bottom
PC101  -  [MX_C0805_SMALL]  9.41 46.48 270 bottom
PC102  -  [MX_C0805_SMALL]  7.64 46.48 270 bottom
PC103  -  [MX_C0805_SMALL]  5.81 46.48 270 bottom
PC104  -  [MX_C0805_SMALL]  3.99 46.49 270 bottom
PC105  -  [MX_C0603]  16.48 38.11 270 top
PC106  -  [MX_C0603]  11.7 44.9 90 top
PC107  -  [MX_C0603]  12.99 44.9 90 top
PC108  -  [MX_C0603]  14.28 44.9 90 top
PC109  -  [MX_C0603]  9.12 44.9 90 top
PC110  -  [MX_C0603]  10.41 44.9 90 top
PC111  -  [MX_C0402]  132.46 41.15 0 bottom
PC113  -  [MX_C0805_SMALL]  128.35 39.08 90 bottom
PC114  -  [MX_C0805_SMALL]  124.63 43.44 0 bottom
PC115  -  [MX_C0603_SMALL]  122.05 66.26 180 bottom
PC116  -  [MX_C0603]  127.31 63.17 180 bottom
PC117  -  [MX_C0603]  123.79 67.1 90 bottom
PC118  -  [MX_C0402]  127.1 46.01 0 bottom
PC119  -  [MX_C0603]  122.51 59.12 270 top
PC121  -  [MX_C0402]  135.34 46.7 0 bottom
PC122  -  [MX_C0603]  132.31 43.09 270 bottom
PC123  -  [MX_C0603]  127.3 60.63 180 bottom
PC124  -  [MX_C0402_SMALL]  124.84 66.5 270 bottom
PC125  -  [MX_C0603]  130.13 64.86 180 bottom
PC126  -  [MX_C0603]  127.3 61.9 0 bottom
PC127  -  [MX_C0402_SMALL]  124.69 57.55 270 top
PC128  -  [MX_C0402_SMALL]  124.18 56.34 180 top
PC129  -  [MX_C0603]  127.14 66.97 90 bottom
PC131  -  [MX_C0805_SMALL]  111.66 43.37 0 bottom
PC132  -  [MX_C0805_SMALL]  111.67 41.6 0 bottom
PC133  -  [MX_C0402]  118.63 41.13 0 bottom
PC134  -  [MX_C0603]  118.9 63.27 0 bottom
PC135  -  [MX_C0402]  114.25 45.95 0 bottom
PC136  -  [MX_C0402_SMALL]  125.38 60.13 90 bottom
PC138  -  [MX_C0402_SMALL]  120.29 61.19 0 bottom
PC139  -  [MX_C0402]  122.74 46.73 0 bottom
PC140  -  [MX_C0402_SMALL]  120.09 59.2 270 top
PC141  -  [MX_C0402_SMALL]  120.5 57.95 0 top
PC142  -  [MX_C0805_SMALL]  109.15 45.55 180 bottom
PC143  -  [MX_C0402]  109 41.1 0 bottom
PC144  -  [MX_C0603_SMALL]  106.99 61.96 0 top
PC145  -  [MX_C0402]  103.36 48.39 0 bottom
PC147  -  [MX_C0805_SMALL]  109.14 47.35 180 bottom
PC148  -  [MX_C0603_SMALL]  109.09 57.76 270 top
PC149  -  [MX_C0402_SMALL]  111.59 65.99 90 top
PC150  -  [MX_C0603_SMALL]  105.52 61.45 0 bottom
PC151  -  [MX_C0402_SMALL]  110.7 66.02 270 top
PC152  -  [MX_C0402]  109.87 53.28 270 bottom
PC153  -  [MX_C0603]  109.29 49.67 270 bottom
PC154  -  [MX_C0402_SMALL]  113.21 63.89 270 top
PC155  -  [MX_C0402_SMALL]  115.98 64.33 270 top
PC156  -  [MX_C0603_SMALL]  112.55 58.15 270 top
PC157  -  [MX_C0603_SMALL]  115.05 59.04 270 top
PC158  -  [MX_C0603_SMALL]  113.81 59.04 270 top
PC159  -  [MX_C0402_SMALL]  114.33 61.42 180 top
PC160  -  [MX_C0603]  120.4 10.03 0 bottom
PC161  -  [MX_C0805_SMALL]  122.61 6.95 90 bottom
PC162  -  [MX_C0603]  116.73 7.92 270 bottom
PC163  -  [MX_C0805_SMALL]  124.38 6.95 90 bottom
PC164  -  [MX_C0805_SMALL]  106.74 4.51 90 bottom
PC165  -  [MX_C0805_SMALL]  106.38 8.42 0 bottom
PC166  -  [MX_C0805_SMALL]  106.38 10.15 0 bottom
PC167  -  [MX_C0805_SMALL]  108.49 4.51 90 bottom
PC168  -  [MX_C0402]  115.11 4.84 0 bottom
PC169  -  [MX_C0402]  127.92 6.21 90 bottom
PC170  -  [MX_C0603]  119.48 14.34 90 top
PC171  -  [MX_C0402]  117.81 3.52 0 bottom
PC172  -  [MX_C0402_SMALL]  120.5 17.06 270 top
PC174  -  [MX_C0603]  47.94 7.46 270 bottom
PC175  -  [MX_C0603]  49.45 15.17 90 bottom
PC176  -  [MX_C0603]  47.38 15.15 90 bottom
PC177  -  [MX_C0402_SMALL]  46.36 7.31 180 bottom
PC182  -  [MX_C0603_SMALL]  127.63 56.7 180 bottom
PC184  -  [MX_C0603_SMALL]  130.1 59.72 180 bottom
PC185  -  [MX_C0402_SMALL]  47.98 88.05 270 bottom
PC186  -  [MX_C0402_SMALL]  42.88 90.01 270 bottom
PC187  -  [MX_C0603_SMALL]  117.71 57.9 90 bottom
PC188  -  [MX_C0603_SMALL]  116.22 61.17 90 bottom
PC189  -  [MX_C0603_SMALL]  112.46 57.69 180 bottom
PC190  -  [MX_C0402_SMALL]  54.7 88.23 90 bottom
PC194  -  [MX_C0603_SMALL]  134.67 55.72 0 bottom
PC195  -  [MX_C0603]  133.69 58.48 0 top
PC196  -  [MX_C0603]  133.68 57.14 0 top
PC197  -  [MX_C0402_SMALL]  150.42 75.32 0 bottom
PC198  -  [MX_C0805_SMALL]  141.93 70.78 270 bottom
PC199  -  [MX_C0603]  119.5 43.06 270 bottom
PC200  -  [MX_C0603_SMALL]  127.63 57.94 180 bottom
PC201  -  [MX_C0603_SMALL]  44.92 85.12 90 bottom
PC202  -  [MX_C0603]  42.47 86.46 0 bottom
PC203  -  [MX_C0603]  45.8 83.15 0 bottom
PC213  -  [MX_C0603_SMALL]  127.63 55.44 180 bottom
PC218  -  [MX_C0603_SMALL]  124.08 54.27 0 bottom
PC219  -  [MX_C0402]  37.44 20.47 90 bottom
PC220  -  [MX_C0402]  28.45 62.49 0 top
PC221  -  [MX_C0603]  12.54 38.11 270 top
PC222  -  [MX_C0603]  13.86 38.11 270 top
PC223  -  [MX_C0603_SMALL]  97.31 41.37 270 bottom
PC224  -  [MX_C0603_SMALL]  102.92 42.74 90 bottom
PC225  -  [MX_C0603_SMALL]  99.34 39.21 180 bottom
PCE1  -  [MX_C3528]  55.03 72.27 270 bottom
PCE2  -  [MX_C3528]  17.86 72.83 0 bottom
PCE3  -  [MX_C3528]  15.18 38.54 90 bottom
PCE5  -  [MX_C3528]  135.68 58.43 180 bottom
PCE6  -  [MX_C3528]  121.91 56.7 180 bottom
PCE7  -  [MX_C7343D_H79]  96.86 55.99 90 bottom
PD1  -  [MX_U_DFN3030_8P_26_118X118]  12.97 58.62 90 top
PD2  -  [MX_U_DFN3030_8P_26_118X118]  8.05 57.55 0 top
PD3  -  [MX_SOT323]  143.58 41.48 0 bottom
PD4  -  [MX_SOT323]  142.02 56.11 270 bottom
PD5  -  [MX_SOD323_H37]  8.97 17.64 270 top
PD6  -  [MX_SOT323]  130.46 62.98 180 bottom
PD7  -  [MX_SOT323]  130.14 66.75 0 bottom
PD8  -  [MX_SC_75A_ROHM]  163.07 66.67 0 top
PF1  -  [MX_FUSE_2P_125X60_H23]  163.78 13.65 0 top
PJP2  -  [TV_RTC_SHORT_6X20]  13.95 65.84 90 top
PJP3  -  [TV_RTC_SHORT_6X20]  13.98 65 270 top
PJP4  -  [TV_RTC_SHORT_6X20]  133.7 69.77 270 bottom
PJP5  -  [TV_RTC_SHORT_6X20]  133.68 70.6 90 bottom
PJP6  -  [TV_RTC_SHORT_6X20]  10.66 38.69 0 top
PJP7  -  [TV_RTC_SHORT_6X20]  10.69 37.41 0 top
PJP8  -  [TV_RTC_SHORT_6X20]  6.78 26.79 180 bottom
PJP9  -  [TV_RTC_SHORT_6X20]  4.99 38.19 270 bottom
PJP10  -  [TV_RTC_SHORT_6X20]  4.86 41.6 90 bottom
PJP11  -  [TV_RTC_SHORT_6X20]  134.89 58.83 180 bottom
PJP12  -  [TV_RTC_SHORT_6X20]  134.9 57.97 180 bottom
PJP13  -  [TV_RTC_SHORT_6X20]  121.13 57.03 180 bottom
PJP14  -  [TV_RTC_SHORT_6X20]  97.02 60.33 90 bottom
PJP15  -  [TV_RTC_SHORT_6X20]  109.28 5.35 0 bottom
PJP16  -  [TV_RTC_SHORT_6X20]  106.76 10.13 180 bottom
PL1  -  [MX_L0603]  14.94 83.08 270 bottom
PL2  -  [MX_L0603]  16.26 83.08 270 bottom
PL3  -  [MX_L0603]  52.53 72.43 270 bottom
PL4  -  [MX_L0603]  20.12 75.28 180 bottom
PL5  -  [MX_L0603]  12.72 37.28 90 bottom
PL7  -  [MX_L0805_H41]  80.23 6.3 0 bottom
PL8  -  [MX_L0805_H41]  80.21 4.16 0 bottom
PL9  -  [MX_INDUCTOR_2P_274X260]  137.1 63.91 180 bottom
PL10  -  [3MM_OPEN_5MIL_M1M2]  3.35 21.32 180 bottom
PL12  -  [MX_INDUCTOR_2P_278X260_H118]  4.86 39.91 90 bottom
PL13  -  [MX_L0805_H43]  129.32 41.64 180 bottom
PL14  -  [MX_INDUCTOR_2P_287X260]  130 51.19 0 bottom
PL15  -  [MX_L0805_H43]  115.44 41.7 180 bottom
PL16  -  [MX_INDUCTOR_2P_287X260]  118.19 51.28 0 bottom
PL17  -  [MX_L0805_H43]  106.72 42.8 90 bottom
PL18  -  [MX_INDUCTOR_2P_287X260]  102.96 56.13 90 bottom
PL19  -  [MX_L0805_H43]  126.32 5.76 90 bottom
PL20  -  [MX_INDUCTOR_2P_205X185]  112.62 8.37 180 bottom
PQ1  -  [MX_SOT23_2D4_H44]  55.73 82.11 0 bottom
PQ5  -  [MX_SOT363]  63.3 89.51 90 bottom
PQ6  -  [MX_SOT363]  63.68 86.33 0 bottom
PQ7  -  [MX_SOT23_H43]  99.98 36.9 0 bottom
PQ8  -  [MX_SOT23_H43]  96.12 37.89 90 bottom
PQ9  -  [MX_SOT363]  136.83 38.4 0 top
PQ10  -  [MX_SOT363]  139.5 38.4 0 top
PQ11  -  [MX_SO_8FL_COLAY]  8.46 65.19 180 top
PQ12  -  [MX_DFN_6P_26_79X79_2PAD_IR]  13.77 68.75 180 top
PQ13  -  [MX_SOT363]  140.14 43.36 90 bottom
PQ14  -  [MX_DFN_6P_26_79X79_2PAD_IR]  137.89 69.03 180 bottom
PQ15  -  [MX_DFN_6P_26_79X79_2PAD_IR]  143.23 65.64 270 bottom
PQ16  -  [MX_DFN_6P_26_79X79_2PAD_IR]  143.14 62.09 270 bottom
PQ17  -  [MX_DFN_6P_26_79X79_2PAD_IR]  127.58 44.09 90 bottom
PQ18  -  [MX_DFN_6P_26_79X79_2PAD_IR]  132.8 46.1 0 bottom
PQ19  -  [MX_DFN_6P_26_79X79_2PAD_IR]  114.76 44.02 90 bottom
PQ20  -  [MX_DFN_6P_26_79X79_2PAD_IR]  119.97 45.95 0 bottom
PQ21  -  [MX_DFN_6P_26_79X79_2PAD_IR]  106.13 47.48 180 bottom
PQ22  -  [MX_DFN_6P_26_79X79_2PAD_IR]  108 52.79 0 bottom
PQ24  -  [MX_SOT23_2D4_H44]  130.77 56.98 0 bottom
PQ25  -  [MX_SOT323_S5]  47.93 85.44 90 bottom
PQ26  -  [MX_SOT23_2D4_H55]  45.43 88.9 270 bottom
PQ27  -  [MX_SOT23_2D4_H44]  115.32 57.03 0 bottom
PQ28  -  [MX_SOT23_H43]  52.08 88.42 0 bottom
PQ30  -  [MX_DFN_6P_26_79X79_2PAD_IR]  130.03 57.99 0 top
PQ31  -  [MX_SOT323_S5]  131.52 19.12 90 top
PQ32  -  [MX_SOT323_S5]  127.26 59.53 0 top
PQ33  -  [MX_SOT23_2D4_H44]  42.2 84.03 90 bottom
PQ34  -  [MX_SOT23_2D4_H55]  165.55 63.16 180 top
PQ35  -  [MX_SOT323_S5]  104.5 38.83 180 bottom
PQ36  -  [MX_SOT23_2D4_H44]  100.1 41.65 90 bottom
PR2  -  [MX_R0402]  49.94 69.26 180 bottom
PR3  -  [MX_R0402_SHORT]  38.03 72.25 270 bottom
PR7  -  [MX_R0402]  33.38 74.9 90 bottom
PR8  -  [MX_R0402_SMALL]  29.11 75.31 270 top
PR10  -  [MX_R0402_SHORT]  36.16 72.51 270 bottom
PR11  -  [MX_R0402_SHORT]  50.53 72.44 270 bottom
PR12  -  [MX_R0402]  47.07 76.24 270 top
PR13  -  [MX_R0402]  51.03 76.19 270 bottom
PR14  -  [MX_R0402_SHORT]  37.91 83.28 90 bottom
PR15  -  [MX_R0402]  38.02 70.82 90 top
PR16  -  [MX_R0402]  36.72 83.28 90 bottom
PR18  -  [MX_R0402]  52.09 75.47 90 bottom
PR20  -  [MX_R0402]  39.96 74.62 270 top
PR21  -  [MX_R0402_SHORT]  44.95 75.22 90 top
PR22  -  [MX_R0402_SHORT]  43.11 71.85 90 top
PR24  -  [MX_R0402_SHORT]  43.55 75.88 90 top
PR26  -  [MX_R0402]  46.69 72.23 270 top
PR29  -  [MX_R0402]  37.93 72.5 180 top
PR30  -  [MX_R0402]  45.65 69.79 270 top
PR31  -  [MX_R0402]  36.99 70.03 270 top
PR32  -  [MX_R0805]  17.35 78.96 270 top
PR33  -  [MX_R0402]  44.37 73.71 180 bottom
PR35  -  [MX_R0402]  20.36 71.68 90 top
PR36  -  [MX_R0402]  42.69 74.68 270 bottom
PR37  -  [MX_R0402]  33.76 77.21 270 top
PR40  -  [MX_R0402]  48.69 79.72 270 bottom
PR41  -  [MX_R0402]  49.17 82.31 270 bottom
PR42  -  [MX_R0805]  51.74 80.68 180 bottom
PR43  -  [MX_R0402]  34.95 56.86 90 top
PR44  -  [MX_R0402]  54.31 70.48 90 top
PR45  -  [MX_R0402]  27.05 76.77 0 bottom
PR46  -  [MX_R0402]  27.02 79.98 0 bottom
PR49  -  [MX_R0402]  55.68 84.8 180 bottom
PR50  -  [MX_R0402]  60.5 90.31 0 bottom
PR52  -  [MX_R0402]  65.5 89.61 270 bottom
PR53  -  [MX_R0402]  60.38 86.96 270 bottom
PR54  -  [MX_R0402]  61.44 86.96 90 bottom
PR55  -  [MX_R0402_SMALL]  117.3 89.65 0 bottom
PR56  -  [MX_R0402_SMALL]  67.22 85.44 270 bottom
PR57  -  [MX_R0402_SMALL]  14.56 69.32 0 bottom
PR58  -  [MX_R0603_SMALL]  11.5 50.54 270 top
PR59  -  [MX_R0603_SMALL]  11.61 52.45 0 top
PR60  -  [MX_R0603_SMALL]  11.61 56.11 0 top
PR61  -  [MX_R0603_SMALL]  11.61 54.93 0 top
PR62  -  [MX_R0603_SMALL]  11.61 53.63 0 top
PR63  -  [MX_R0603_SMALL]  15.17 55.84 0 top
PR64  -  [MX_R0603_SMALL]  15.17 52.04 0 top
PR65  -  [MX_R0603_SMALL]  15.17 54.6 0 top
PR66  -  [MX_R0603_SMALL]  15.17 53.38 0 top
PR67  -  [MX_R0402_SMALL]  141.19 40.5 180 top
PR68  -  [MX_R0402_SMALL]  136.11 36.21 0 top
PR69  -  [MX_R0402_SMALL]  135.4 40.84 90 top
PR70  -  [MX_R0402_SMALL]  139.98 35.48 180 top
PR71  -  [MX_R0402_SMALL]  136.66 41.78 0 top
PR72  -  [MX_R0402_SMALL]  139.98 36.31 0 top
PR73  -  [MX_R0805_H24_SMALL]  147.27 40.99 180 top
PR74  -  [MX_R1508]  14.09 65.4 270 top
PR75  -  [MX_R0402_SMALL]  138.66 47.39 90 bottom
PR76  -  [MX_R0402_SMALL]  139.52 47.39 90 bottom
PR77  -  [MX_R0402]  137.72 43.24 270 bottom
PR78  -  [MX_R1206]  143.23 45.2 90 bottom
PR79  -  [MX_R0402]  147.14 39.59 180 top
PR80  -  [MX_R0402_SMALL]  137.05 55.72 270 bottom
PR81  -  [MX_R0402_SMALL]  135.84 52.92 0 bottom
PR82  -  [MX_R0402_SMALL]  136.37 51.08 0 bottom
PR83  -  [MX_R0402_SMALL]  137.71 45.36 90 bottom
PR84  -  [MX_R0402_SMALL]  137.98 54.85 90 bottom
PR85  -  [MX_R0402_SMALL]  136.37 48.22 0 bottom
PR86  -  [MX_R0805_SMALL]  144.38 55.87 90 bottom
PR87  -  [MX_R0402_SMALL]  136.22 55.72 90 bottom
PR88  -  [MX_R0402_SMALL]  137.11 53.38 90 bottom
PR89  -  [MX_R0402_SMALL]  136.37 51.92 180 bottom
PR90  -  [MX_R0402_SMALL]  137.6 47.41 270 bottom
PR91  -  [MX_R0402_SMALL]  143.33 63.9 180 bottom
PR92  -  [MX_R1508]  133.47 70.17 90 bottom
PR94  -  [MX_R0805_SMALL]  143.84 59.28 90 bottom
PR95  -  [MX_R0402_SMALL]  140.8 55.83 90 top
PR96  -  [MX_R0402]  139.54 54.47 180 bottom
PR97  -  [MX_R0603_SMALL]  6.62 16.67 0 bottom
PR98  -  [MX_R0402]  12.15 11.53 90 bottom
PR99  -  [MX_R0402]  13.24 11.53 90 bottom
PR100  -  [MX_R0402]  10.92 14.03 90 bottom
PR101  -  [MX_R0402]  9.86 13.69 270 bottom
PR102  -  [MX_R0402]  7.63 21.8 0 bottom
PR103  -  [MX_R0603_SMALL]  13.76 11.22 90 top
PR104  -  [MX_R0402]  13.47 13.88 270 bottom
PR105  -  [MX_R0402]  12.16 14.03 270 bottom
PR106  -  [MX_R0402]  17.02 23.44 270 bottom
PR107  -  [MX_R0402]  7.63 20.76 0 bottom
PR109  -  [MX_R0402]  6.87 19.6 0 bottom
PR110  -  [MX_R0402]  6.87 18.58 0 bottom
PR111  -  [MX_R0805_H26_SMALL]  9.93 36.8 180 bottom
PR112  -  [MX_R0402_SMALL]  10.47 38.94 90 bottom
PR113  -  [MX_R0402]  20.56 18.84 270 top
PR114  -  [MX_R0402]  17.23 13.39 0 top
PR115  -  [MX_R0402]  15.31 11.34 90 top
PR116  -  [MX_R0402]  17.76 11.59 90 top
PR117  -  [MX_R0402]  18.68 18.53 180 bottom
PR118  -  [MX_R0402]  15.83 23.13 270 bottom
PR119  -  [MX_R0402]  16.54 26.13 90 bottom
PR120  -  [MX_R0402]  14.17 27.04 90 bottom
PR121  -  [MX_R0402]  11.14 23.42 270 bottom
PR122  -  [MX_R0402]  12.06 26.77 90 bottom
PR123  -  [MX_R0402]  9.99 23.43 270 bottom
PR124  -  [MX_R0402]  11.04 26.66 270 bottom
PR125  -  [MX_R0402]  8.83 23.43 270 bottom
PR126  -  [MX_R0402]  9.97 26.77 90 bottom
PR127  -  [MX_R0402]  12.28 24.3 270 bottom
PR128  -  [MX_R0402]  18.85 14.98 180 bottom
PR129  -  [MX_R0402]  13.1 26.77 90 bottom
PR130  -  [MX_R0402]  18.65 13.78 180 bottom
PR131  -  [MX_R0402]  18.84 16.14 180 bottom
PR132  -  [MX_R0402]  9.36 19.12 180 bottom
PR133  -  [MX_R0402]  18.65 17.33 180 bottom
PR134  -  [MX_R0402_SMALL]  3.28 33.44 180 bottom
PR136  -  [MX_R0805_H24_SMALL]  2.77 25.6 180 bottom
PR137  -  [MX_R1206]  6.53 34.21 0 bottom
PR138  -  [MX_R0805_SMALL]  121.82 68.32 270 bottom
PR139  -  [MX_R0805_SMALL]  126.95 64.66 0 bottom
PR140  -  [MX_R0805_SMALL]  125.21 45.85 270 bottom
PR141  -  [MX_R0402_SMALL]  127.02 47.01 0 bottom
PR142  -  [MX_R1206]  130.31 45.09 270 bottom
PR143  -  [MX_R0805_SMALL]  135.28 44.69 90 bottom
PR144  -  [MX_R0402]  119.98 62.11 0 bottom
PR146  -  [MX_R0603_SMALL]  125.88 66.74 90 bottom
PR147  -  [MX_R0402_SMALL]  123.81 57.55 90 top
PR148  -  [MX_R0402_SMALL]  123.81 59.32 270 top
PR149  -  [MX_R0402]  124.77 59.81 90 top
PR150  -  [MX_R0805_SMALL]  119.18 64.8 180 bottom
PR151  -  [MX_R0805_SMALL]  112.29 45.79 270 bottom
PR152  -  [MX_R0402]  121.16 60.22 0 bottom
PR153  -  [MX_R0402_SMALL]  114.11 46.87 0 bottom
PR154  -  [MX_R0402]  125.51 58.02 90 bottom
PR155  -  [MX_R0402]  118.01 60.97 0 bottom
PR156  -  [MX_R0805_SMALL]  122.16 44.73 90 bottom
PR158  -  [MX_R0402_SMALL]  120.93 59.17 90 top
PR159  -  [MX_R0402_SMALL]  119.24 59.2 270 top
PR160  -  [MX_R0805_SMALL]  110.72 56.98 270 top
PR161  -  [MX_R0402_SMALL]  103.28 47.43 0 bottom
PR162  -  [MX_R0402]  114.3 65.65 180 top
PR163  -  [MX_R0402]  112.53 66.17 270 top
PR164  -  [MX_R0603_SMALL]  106.99 63.34 0 top
PR165  -  [MX_R0402]  108.86 66.09 270 top
PR166  -  [MX_R0805_SMALL]  103.35 45.56 90 bottom
PR167  -  [MX_R1206]  106.16 50.13 0 bottom
PR168  -  [MX_R0402_SMALL]  109.8 66.02 270 top
PR169  -  [MX_R0805_SMALL]  109.49 55.72 270 bottom
PR171  -  [MX_R0402]  106.94 64.48 180 top
PR172  -  [MX_R0402]  107.43 66.17 270 top
PR173  -  [MX_R0402]  114.18 63.99 270 top
PR174  -  [MX_R0402_SMALL]  115.13 64.33 90 top
PR175  -  [MX_R0402]  107.58 60.14 270 top
PR176  -  [MX_R0402_SMALL]  114.33 60.55 180 top
PR178  -  [MX_R0805_H24_SMALL]  117.54 10.21 180 bottom
PR179  -  [MX_R0402]  116.59 5.25 90 bottom
PR180  -  [MX_R0402]  120.77 13.99 270 top
PR181  -  [MX_R0402_SMALL]  117.2 11.98 90 top
PR182  -  [MX_R0402_SMALL]  119.76 12.44 180 top
PR184  -  [MX_R0402_SMALL]  122.53 3.42 180 bottom
PR185  -  [MX_R0402]  118.9 16.98 180 top
PR186  -  [MX_R0402]  118.11 14.88 90 top
PR189  -  [MX_R0402_SMALL]  45.54 14.22 180 bottom
PR191  -  [MX_R0402]  45.57 15.21 0 bottom
PR195  -  [MX_R0402_SMALL]  128.14 59 0 bottom
PR196  -  [MX_R0402]  48.95 88.03 90 bottom
PR197  -  [MX_R0402]  51.06 86.28 0 bottom
PR198  -  [MX_R0402_SMALL]  112.71 56.11 0 bottom
PR199  -  [MX_R0402]  48.74 89.7 0 bottom
PR200  -  [MX_R0402]  55.6 89.67 180 bottom
PR203  -  [MX_R0402]  132.23 21.15 0 top
PR206  -  [MX_R0402_SMALL]  132.66 55.63 90 top
PR207  -  [MX_R0402_SMALL]  126.16 19.17 270 top
PR209  -  [MX_R0402]  127.28 63.92 270 top
PR212  -  [MX_R0402_SMALL]  130.75 55.7 270 top
PR214  -  [MX_R1206]  117.46 45.19 270 bottom
PR216  -  [MX_R0402_SHORT]  34.38 77.15 90 bottom
PR217  -  [MX_R0402]  7.77 23.48 270 bottom
PR220  -  [MX_R0402]  47.04 78.65 270 top
PR221  -  [MX_R0402]  34.38 69.82 90 top
PR223  -  [MX_R0402_SMALL]  45.67 82.01 180 bottom
PR224  -  [MX_R0402]  13.28 22.65 270 bottom
PR226  -  [MX_R0402]  165.68 67.86 180 top
PR227  -  [MX_R0402]  135.46 78.71 270 top
PR228  -  [MX_R0402]  33.72 74.56 90 top
PR229  -  [MX_R0402]  134.95 80.48 180 top
PR231  -  [MX_R0402]  153.87 18.41 270 top
PR232  -  [MX_R0402]  152.85 18.41 270 top
PR233  -  [MX_R0402_SMALL]  95.84 86.45 0 bottom
PR234  -  [TV_RTC_SHORT_6X20]  91.67 52.49 180 top
PR235  -  [MX_R0402_SMALL]  102.64 39.02 270 bottom
PR236  -  [MX_R0402_SMALL]  108.1 35.58 180 bottom
PR238  -  [MX_R0402_SMALL]  101.3 39.44 180 bottom
PR239  -  [MX_R0402_SMALL]  108.1 36.87 180 bottom
PR241  -  [MX_R0402_SMALL]  106.05 35.93 270 bottom
PR242  -  [MX_R0402]  32.46 78.58 270 top
PR243  -  [MX_R0402]  31.42 78.58 270 top
PRT1  -  [MX_R0402_SMALL]  115.11 14.47 180 top
PRT2  -  [MX_R0402_SMALL]  66.38 85.44 270 bottom
PRT3  -  [MX_R0402_SMALL]  15.93 70.59 0 bottom
PRT4  -  [MX_R0402_SMALL]  9.02 38.94 270 bottom
PRT5  -  [MX_R0402]  9.46 34.44 270 bottom
PT2  -  [MX_TPC26B_S4_68]  30.2 58.36 180 bottom
PT4  -  [MX_TPC26B_S4_68]  32.82 60.16 180 bottom
PT6  -  [MX_TPC26B_S4_68]  26.32 57.52 180 bottom
PT7  -  [MX_TPC26B_S4_68]  28.5 57.93 180 bottom
PT8  -  [MX_TPC26B_S4_68]  30.51 54.83 180 bottom
PU3  -  [MX_QFN_20P_20_S138_PAD_4V]  140.29 50.89 180 bottom
PU4  -  [MX_QFN_32P_16_S157_P_H39_4V]  14.03 18.49 90 bottom
PU5  -  [MX_SOP_9P_16_177X138_9V]  4.99 30.82 0 bottom
PU6  -  [MX_QFN_20P_16_S118_PAD_2V]  123.4 62.83 180 bottom
